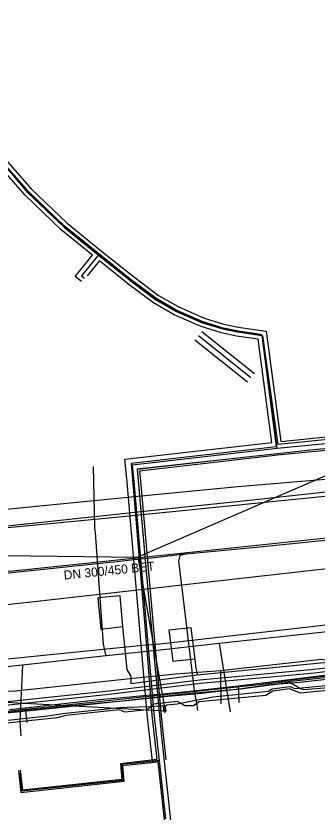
# Model space of a CAD drawing. Extents: x -600309 to -598967, y -1161267 to -1160292.
# Drawn here: x -599198.7 to -599172, y -1160445.7 to -1160375.2 of the extents above; entities that cross this region are included whole.
import ezdxf

# ---------------------------------------------------------------- set-up
doc = ezdxf.new("R2010")
doc.units = 0
for name, color, linetype in [('Vrstva 12', 7, 'Continuous'), ('Vrstva 13', 7, 'Continuous'), ('Vrstva 19', 7, 'Continuous'), ('Vrstva 25', 7, 'Continuous'), ('Vrstva 26', 7, 'Continuous'), ('Vrstva 29', 7, 'Continuous'), ('Vrstva 30', 7, 'Continuous'), ('Vrstva 37', 7, 'Continuous'), ('Vrstva 42', 7, 'Continuous'), ('Vrstva 44', 7, 'Continuous'), ('Vrstva 51', 7, 'Continuous'), ('Vrstva 54', 7, 'Continuous'), ('Vrstva 55', 7, 'Continuous'), ('Vrstva 58', 7, 'Continuous'), ('Vrstva 9', 7, 'Continuous')]:
    doc.layers.add(name, color=color, linetype=linetype)

msp = doc.modelspace()

# ---------------------------------------------------------------- linework, layer by layer
at = {"layer": 'Vrstva 12'}
for points in [[(-599159.73, -1160416.58), (-599172.75, -1160417.89), (-599175.74, -1160418.2), (-599179.22, -1160418.55), (-599185.69, -1160419.2), (-599191.36, -1160419.77)], [(-599215.54, -1160422.07), (-599183.99, -1160418.7), (-599177.99, -1160418.06), (-599168.25, -1160417.02), (-599166.51, -1160416.87)], [(-599191.36, -1160419.77), (-599215.54, -1160422.07)], [(-599156.38, -1160431.75), (-599177.29, -1160434.36)], [(-599166.63, -1160433.18), (-599175.04, -1160434.11), (-599177.29, -1160434.36)], [(-599177.29, -1160434.36), (-599178.99, -1160434.55)], [(-599184.72, -1160435.16), (-599186.42, -1160435.32)], [(-599183.23, -1160435.02), (-599184.72, -1160435.16)], [(-599178.99, -1160434.55), (-599182.96, -1160435), (-599183.23, -1160435.02)], [(-599178.99, -1160434.55), (-599178.92, -1160436.01)], [(-599188.61, -1160435.52), (-599191.28, -1160435.77), (-599197.85, -1160436.5)], [(-599186.42, -1160435.32), (-599188.61, -1160435.52)], [(-599197.85, -1160436.5), (-599199.24, -1160436.65)], [(-599197.85, -1160436.5), (-599197.73, -1160437.78)]]:
    msp.add_lwpolyline(points, dxfattribs=at)
at = {"layer": 'Vrstva 13'}
msp.add_line((-599180.669, -1160430.786), (-599179.696, -1160436.841), dxfattribs=at)
for points in [[(-599190.684, -1160431.876), (-599190.766, -1160431.5), (-599190.916, -1160430.824), (-599191.624, -1160420.957), (-599191.685, -1160420.493), (-599191.81, -1160415.087)], [(-599266.29, -1160439), (-599265.75, -1160438.92), (-599254.31, -1160437.84), (-599242.55, -1160436.65), (-599224.43, -1160434.75), (-599206.75, -1160432.86), (-599187.429, -1160430.934), (-599185.94, -1160430.79), (-599176.34, -1160429.72), (-599164.53, -1160428.34), (-599160.25, -1160427.86), (-599155.91, -1160427.47), (-599154.382, -1160427.282)], [(-599149.54, -1160427.41), (-599153.011, -1160427.773), (-599153.26, -1160427.8), (-599160.957, -1160428.64), (-599180.669, -1160430.786), (-599185.884, -1160431.357), (-599187.377, -1160431.521), (-599190.684, -1160431.876), (-599198.113, -1160432.685), (-599222.346, -1160435.322), (-599251.335, -1160438.478), (-599265.5, -1160440.02), (-599266.034, -1160440.08)], [(-599198.113, -1160432.685), (-599198.348, -1160437.726), (-599198.25, -1160438.947)]]:
    msp.add_lwpolyline(points, dxfattribs=at)
at = {"layer": 'Vrstva 19'}
for points in [[(-599185.219, -1160423.02), (-599184.89, -1160422.97), (-599184.02, -1160422.87), (-599183.6, -1160422.83), (-599176.76, -1160422.18), (-599169.86, -1160421.48), (-599162.91, -1160420.74), (-599159.94, -1160420.4), (-599159.46, -1160420.35), (-599158.7, -1160420.24), (-599157.37, -1160420.1), (-599154.21, -1160419.74), (-599153.17, -1160419.62), (-599152.28, -1160419.52), (-599151.55, -1160419.44)], [(-599189.94, -1160423.53), (-599189.51, -1160423.49), (-599188.21, -1160423.34), (-599186.92, -1160423.2), (-599185.62, -1160423.06), (-599185.219, -1160423.02)], [(-599183.6, -1160422.83), (-599184.16, -1160422.97), (-599184.28, -1160423.44), (-599183.09, -1160433.19), (-599182.95, -1160434.4), (-599182.91, -1160434.67), (-599182.91, -1160434.72), (-599182.89, -1160434.84), (-599182.87, -1160434.97), (-599182.69, -1160436.05), (-599182.58, -1160436.71)], [(-599254.51, -1160430.31), (-599245.92, -1160429.36), (-599243.04, -1160429.08), (-599229.67, -1160427.65), (-599217.1, -1160426.32), (-599203.43, -1160424.93), (-599200.2, -1160424.61), (-599192.59, -1160423.81), (-599191.52, -1160423.69), (-599190.92, -1160423.63), (-599190.43, -1160423.58), (-599189.94, -1160423.53)]]:
    msp.add_lwpolyline(points, dxfattribs=at)
at = {"layer": 'Vrstva 25'}
for p, q in [((-599161.519, -1160412.108), (-599175.528, -1160413.501)), ((-599185.993, -1160441.133), (-599185.429, -1160446.319))]:
    msp.add_line(p, q, dxfattribs=at)
for points in [[(-599191.346, -1160396.32), (-599194.404, -1160393.82), (-599197.616, -1160390.754), (-599199.666, -1160388.406), (-599200.989, -1160386.783), (-599209.232, -1160391.952), (-599215.053, -1160395.52), (-599219.636, -1160397.611), (-599223.7, -1160398.633), (-599236.871, -1160400.827), (-599242.951, -1160401.557), (-599244.194, -1160401.609), (-599248.324, -1160401.546), (-599253.382, -1160400.553), (-599257.817, -1160398.049), (-599260.079, -1160396.059), (-599264.436, -1160400.845), (-599269.275, -1160406.227), (-599292.639, -1160384.894), (-599305.234, -1160397.5)], [(-599191.346, -1160396.32), (-599192.863, -1160398.187), (-599192.605, -1160398.4)], [(-599175.528, -1160413.501), (-599176.867, -1160403.463), (-599179.051, -1160403.143), (-599180.361, -1160402.861), (-599182.125, -1160402.311), (-599184.484, -1160401.282), (-599186.254, -1160400.26), (-599188.39, -1160398.672), (-599191.346, -1160396.32)], [(-599175.528, -1160413.501), (-599188.376, -1160414.974), (-599188.238, -1160416.414)], [(-599188.238, -1160416.414), (-599186.446, -1160436.975), (-599185.993, -1160441.133)], [(-599185.993, -1160441.133), (-599189.317, -1160441.495), (-599189.166, -1160442.902), (-599198.169, -1160443.872), (-599198.336, -1160442.3)]]:
    msp.add_lwpolyline(points, dxfattribs=at)
at = {"layer": 'Vrstva 26'}
for p, q in [((-599191.285, -1160396.88), (-599192.365, -1160398.208)), ((-599175.209, -1160412.867), (-599161.578, -1160411.51)), ((-599161.46, -1160412.705), (-599175.46, -1160414.097))]:
    msp.add_line(p, q, dxfattribs=at)
for points in [[(-599305.517, -1160397.218), (-599292.651, -1160384.34), (-599269.303, -1160405.66), (-599264.732, -1160400.577), (-599260.11, -1160395.499), (-599257.584, -1160397.721), (-599253.242, -1160400.173), (-599248.282, -1160401.147), (-599244.199, -1160401.209), (-599242.983, -1160401.158), (-599236.928, -1160400.43), (-599223.782, -1160398.241), (-599219.769, -1160397.232), (-599215.242, -1160395.166), (-599209.443, -1160391.612), (-599200.903, -1160386.256), (-599199.361, -1160388.148), (-599197.326, -1160390.477), (-599194.139, -1160393.52), (-599191.092, -1160396.011)], [(-599191.908, -1160396.377), (-599194.669, -1160394.12), (-599197.905, -1160391.031), (-599199.972, -1160388.664), (-599201.076, -1160387.309), (-599209.021, -1160392.292), (-599214.865, -1160395.873), (-599219.504, -1160397.99), (-599223.618, -1160399.025), (-599236.814, -1160401.223), (-599242.918, -1160401.956), (-599244.189, -1160402.01), (-599248.365, -1160401.946), (-599253.522, -1160400.933), (-599258.05, -1160398.377), (-599260.048, -1160396.619), (-599264.139, -1160401.114), (-599269.247, -1160406.795), (-599292.626, -1160385.447), (-599304.951, -1160397.783)], [(-599191.096, -1160396.007), (-599188.146, -1160398.355), (-599186.034, -1160399.925), (-599184.304, -1160400.925), (-599181.985, -1160401.935), (-599180.26, -1160402.474), (-599178.979, -1160402.749), (-599176.511, -1160403.111), (-599175.209, -1160412.867)], [(-599192.859, -1160398.709), (-599193.424, -1160398.242), (-599191.908, -1160396.377)], [(-599176.005, -1160412.952), (-599177.224, -1160403.815), (-599179.122, -1160403.537), (-599180.463, -1160403.248), (-599182.264, -1160402.686), (-599184.665, -1160401.64), (-599186.474, -1160400.595), (-599188.634, -1160398.989), (-599191.285, -1160396.88)], [(-599188.835, -1160416.472), (-599189.03, -1160414.445), (-599176.005, -1160412.952)], [(-599175.46, -1160414.097), (-599187.723, -1160415.503), (-599187.641, -1160416.357)], [(-599186.59, -1160441.198), (-599187.043, -1160437.033), (-599188.836, -1160416.466)], [(-599187.64, -1160416.362), (-599185.849, -1160436.916), (-599185.397, -1160441.068)]]:
    msp.add_lwpolyline(points, dxfattribs=at)
at = {"layer": 'Vrstva 29'}
msp.add_line((-599177.854, -1160407.23), (-599182.506, -1160403.517), dxfattribs=at)
at = {"layer": 'Vrstva 30'}
for p, q in [((-599182.194, -1160403.126), (-599177.542, -1160406.839)), ((-599178.166, -1160407.621), (-599182.818, -1160403.908))]:
    msp.add_line(p, q, dxfattribs=at)
at = {"layer": 'Vrstva 37'}
for points in [[(-599168.806, -1160355.791), (-599166.577, -1160378.573), (-599168.064, -1160378.723), (-599167.911, -1160380.323), (-599166.42, -1160380.169), (-599164.278, -1160401.866), (-599162.592, -1160401.69), (-599161.605, -1160411.763), (-599175.439, -1160413.144), (-599176.797, -1160403.514), (-599177.012, -1160403.403), (-599178.975, -1160403.114), (-599180.425, -1160402.795), (-599182.181, -1160402.24), (-599184.478, -1160401.237), (-599186.279, -1160400.181), (-599188.425, -1160398.582), (-599194.409, -1160393.777), (-599197.565, -1160390.718), (-599199.716, -1160388.279)], [(-599200.984, -1160386.874), (-599197.646, -1160390.813), (-599194.391, -1160393.901), (-599190.914, -1160396.715), (-599188.228, -1160398.851), (-599186.268, -1160400.305), (-599184.45, -1160401.346), (-599182.15, -1160402.347), (-599180.342, -1160402.902), (-599179.045, -1160403.17), (-599176.895, -1160403.495), (-599175.615, -1160413.347), (-599188.47, -1160414.815), (-599187.027, -1160432.066), (-599186.626, -1160437.119), (-599186.186, -1160441.058), (-599189.424, -1160441.425), (-599189.282, -1160442.813), (-599198.082, -1160443.774), (-599198.283, -1160441.997)], [(-599088.539, -1160415.426), (-599122.332, -1160419.036), (-599140.386, -1160421.033), (-599141.325, -1160410.634), (-599141.674, -1160410.408), (-599151.481, -1160411.332), (-599151.839, -1160411.626), (-599162.058, -1160412.619), (-599172.281, -1160413.614), (-599180.114, -1160414.479), (-599187.943, -1160415.343), (-599186.98, -1160426.029)], [(-599186.98, -1160426.029), (-599185.802, -1160438.745), (-599183.829, -1160457.165), (-599196.763, -1160458.819), (-599194.945, -1160472.959), (-599193.092, -1160487.344), (-599191.832, -1160497.004), (-599189.085, -1160518.698), (-599184.645, -1160518.094), (-599182.287, -1160536.371), (-599186.773, -1160536.904), (-599185.919, -1160543.243)], [(-599198.457, -1160442.034), (-599198.247, -1160443.967), (-599189.076, -1160442.981), (-599189.222, -1160441.572), (-599186.106, -1160441.245), (-599184.414, -1160456.718), (-599197.081, -1160458.375), (-599197.31, -1160458.81), (-599193.65, -1160487.388), (-599192.376, -1160497.298), (-599189.502, -1160519.009), (-599189.296, -1160519.241), (-599185.431, -1160518.76), (-599184.944, -1160519.277), (-599182.893, -1160535.5), (-599183.306, -1160535.953), (-599187.068, -1160536.425), (-599187.322, -1160536.835), (-599185.599, -1160549.426), (-599183.312, -1160561.946), (-599181.269, -1160572.198), (-599177.909, -1160571.51)]]:
    msp.add_lwpolyline(points, dxfattribs=at)
at = {"layer": 'Vrstva 42'}
for points in [[(-599168.81, -1160355.79), (-599166.58, -1160378.57), (-599168.06, -1160378.72), (-599167.91, -1160380.32), (-599166.42, -1160380.17), (-599164.28, -1160401.87), (-599162.59, -1160401.69), (-599161.6, -1160411.76), (-599175.44, -1160413.14), (-599176.8, -1160403.51), (-599177.01, -1160403.4), (-599178.98, -1160403.11), (-599180.42, -1160402.8), (-599182.18, -1160402.24), (-599184.48, -1160401.24), (-599186.28, -1160400.18), (-599188.43, -1160398.58), (-599194.41, -1160393.78), (-599197.57, -1160390.72), (-599199.72, -1160388.28)], [(-599204.62, -1160419.36), (-599194.46, -1160418.36), (-599186.67, -1160417.6), (-599179.02, -1160416.87), (-599170.52, -1160416.16), (-599162.01, -1160415.26), (-599159.641, -1160414.949), (-599155.38, -1160414.39), (-599154.85, -1160413.88), (-599154.71, -1160413.29), (-599155.17, -1160410.09), (-599155.66, -1160404.47), (-599155.67, -1160402.75), (-599156.47, -1160395.46), (-599157.68, -1160384.84), (-599157.98, -1160382.06), (-599157.751, -1160381.455), (-599157.593, -1160381.04), (-599157.1, -1160379.74), (-599157.05, -1160379.447), (-599156.92, -1160378.68), (-599157.15, -1160377.67), (-599157.288, -1160377.328), (-599157.49, -1160376.83)], [(-599200.98, -1160386.87), (-599197.65, -1160390.81), (-599194.39, -1160393.9), (-599190.91, -1160396.71), (-599188.23, -1160398.85), (-599186.27, -1160400.31), (-599184.45, -1160401.35), (-599182.15, -1160402.35), (-599180.34, -1160402.9), (-599179.04, -1160403.17), (-599176.89, -1160403.49), (-599175.62, -1160413.35), (-599188.47, -1160414.82), (-599187.03, -1160432.07), (-599186.63, -1160437.12), (-599186.19, -1160441.06), (-599189.42, -1160441.43), (-599189.28, -1160442.81), (-599198.08, -1160443.77), (-599198.28, -1160442)], [(-599088.54, -1160415.43), (-599122.33, -1160419.04), (-599140.39, -1160421.03), (-599141.33, -1160410.63), (-599141.67, -1160410.41), (-599151.48, -1160411.33), (-599151.84, -1160411.63), (-599162.06, -1160412.62), (-599172.28, -1160413.61), (-599180.11, -1160414.48), (-599187.94, -1160415.34), (-599186.98, -1160426.03), (-599185.8, -1160438.75), (-599183.83, -1160457.16), (-599196.76, -1160458.82), (-599194.94, -1160472.96)], [(-599188.51, -1160433.65), (-599188.83, -1160433.07), (-599189.2, -1160429.27), (-599189.45, -1160426.54), (-599191.41, -1160426.72), (-599191.17, -1160429.49), (-599189.2, -1160429.27)], [(-599182.7, -1160433.01), (-599182.8, -1160432.12), (-599183.16, -1160429.38), (-599185.13, -1160429.59), (-599184.76, -1160432.34), (-599182.8, -1160432.12)], [(-599182.7, -1160433.01), (-599182.617, -1160433.552), (-599171.072, -1160432.425), (-599169.629, -1160432.272), (-599166.032, -1160431.909), (-599164.675, -1160431.253), (-599160.068, -1160430.698), (-599159.039, -1160430.839)], [(-599220.527, -1160438.141), (-599190.459, -1160434.977), (-599182.366, -1160433.991), (-599172.256, -1160433.061), (-599164.877, -1160432.162)], [(-599220.527, -1160438.141), (-599190.459, -1160434.977), (-599182.366, -1160433.991), (-599172.256, -1160433.061), (-599164.877, -1160432.162)], [(-599220.495, -1160438.439), (-599190.425, -1160435.275), (-599182.334, -1160434.289), (-599172.224, -1160433.359), (-599164.823, -1160432.458)], [(-599220.495, -1160438.439), (-599190.425, -1160435.275), (-599182.334, -1160434.289), (-599172.224, -1160433.359), (-599164.823, -1160432.458)], [(-599156.887, -1160433.804), (-599156.881, -1160433.343), (-599157.862, -1160433.354), (-599158.455, -1160433.361), (-599164.872, -1160434.096), (-599165.409, -1160434.373), (-599173.447, -1160435.181), (-599174.43, -1160434.776), (-599175.9, -1160434.986), (-599176.534, -1160435.376), (-599182.45, -1160435.954), (-599182.947, -1160436.293), (-599183.704, -1160436.285), (-599184.1, -1160436.064), (-599184.362, -1160435.918), (-599186.496, -1160436.146), (-599186.711, -1160436.346), (-599187.051, -1160436.662), (-599189.025, -1160436.843), (-599189.516, -1160436.644), (-599194.269, -1160437.149), (-599195.02, -1160437.346), (-599200.94, -1160437.987)], [(-599188.51, -1160433.65), (-599188.506, -1160434.319), (-599182.617, -1160433.552)], [(-599203.78, -1160438.04), (-599195.86, -1160437.19), (-599194.305, -1160436.952), (-599189.487, -1160436.44), (-599188.81, -1160436.4), (-599186.711, -1160436.346), (-599186.409, -1160436.338), (-599185.703, -1160436.263), (-599185.657, -1160436.304), (-599185.564, -1160436.761), (-599185.445, -1160436.848), (-599185.368, -1160436.73), (-599185.455, -1160436.321), (-599185.31, -1160436.22), (-599184.404, -1160436.124), (-599184.1, -1160436.064), (-599181.24, -1160435.5), (-599176.296, -1160434.995), (-599175.969, -1160434.794), (-599174.404, -1160434.57), (-599173.952, -1160434.757), (-599167.01, -1160434.07)], [(-599198.46, -1160442.03), (-599198.25, -1160443.97), (-599189.08, -1160442.98), (-599189.22, -1160441.57), (-599186.11, -1160441.24), (-599184.41, -1160456.72), (-599197.08, -1160458.38), (-599197.31, -1160458.81), (-599193.65, -1160487.39), (-599192.38, -1160497.3), (-599189.5, -1160519.01), (-599189.3, -1160519.24), (-599185.43, -1160518.76), (-599184.94, -1160519.28), (-599182.89, -1160535.5), (-599183.31, -1160535.95), (-599187.07, -1160536.42), (-599187.32, -1160536.84), (-599185.6, -1160549.43), (-599183.31, -1160561.95), (-599181.27, -1160572.2), (-599177.91, -1160571.51)]]:
    msp.add_lwpolyline(points, dxfattribs=at)
at = {"layer": 'Vrstva 44'}
msp.add_lwpolyline([(-599206.3, -1160437.6), (-599196.83, -1160436.66), (-599189.27, -1160435.85), (-599183.78, -1160435.23), (-599178.77, -1160434.78), (-599174.5, -1160434.23), (-599174.38, -1160434.24), (-599173.45, -1160434.77), (-599173.16, -1160434.84), (-599171.35, -1160434.71), (-599165.06, -1160433.95), (-599160.31, -1160433.43), (-599160.094, -1160433.043), (-599159.971, -1160432.552), (-599160.094, -1160432.111), (-599160.965, -1160431.324), (-599160.966, -1160431.323)], dxfattribs=at)
at = {"layer": 'Vrstva 51'}
msp.add_lwpolyline([(-599200.27, -1160436.95), (-599197.39, -1160436.65), (-599193.73, -1160436.28), (-599188.6, -1160435.8), (-599185.22, -1160435.44), (-599182.23, -1160435.17), (-599178.89, -1160434.78), (-599176.39, -1160434.45), (-599173.54, -1160434.19), (-599170.59, -1160433.88), (-599167.81, -1160433.53), (-599165.28, -1160433.28), (-599162.93, -1160432.99), (-599160.6, -1160433.01), (-599159.56, -1160433.22), (-599157.53, -1160433.19), (-599153.06, -1160432.68), (-599150.986, -1160433.354), (-599150.14, -1160433.34)], dxfattribs=at)
at = {"layer": 'Vrstva 54'}
for points in [[(-599169.72, -1160415.27), (-599187.89, -1160423.11), (-599185.46, -1160436.78), (-599206.61, -1160435.61), (-599235.92, -1160438.42), (-599255.65, -1160440.37), (-599278.3, -1160442.74)], [(-599164.13, -1160421.49), (-599168.895, -1160421.191), (-599199.21, -1160424.4), (-599206.941, -1160422.893)], [(-599206.941, -1160422.893), (-599187.89, -1160423.11)]]:
    msp.add_lwpolyline(points, dxfattribs=at)
at = {"layer": 'Vrstva 55'}
msp.add_lwpolyline([(-599158.51, -1160377.27), (-599156.45, -1160376.91), (-599152.68, -1160413.45), (-599153.51, -1160415.11), (-599159.08, -1160416.06), (-599158.61, -1160432.05), (-599158.64, -1160432.34), (-599170.407, -1160433.724), (-599170.576, -1160432.141), (-599170.407, -1160433.724), (-599202.89, -1160437.14), (-599203.343, -1160435.509), (-599202.89, -1160437.14), (-599234.882, -1160440.475), (-599235.01, -1160439.55)], dxfattribs=at)
at = {"layer": 'Vrstva 58'}
for points in [[(-599158.05, -1160430.73), (-599160.65, -1160431.2), (-599169.19, -1160432.07), (-599170.594, -1160432.356), (-599171.6, -1160432.2), (-599180.56, -1160433.2)], [(-599180.56, -1160433.2), (-599184.549, -1160433.493), (-599188.02, -1160433.85), (-599198.71, -1160435.01), (-599202.08, -1160435.15), (-599204.03, -1160435.28), (-599208.44, -1160435.95), (-599221.33, -1160437.31), (-599231.04, -1160438.37), (-599232.78, -1160438.66), (-599234.96, -1160438.6), (-599250.03, -1160440.29), (-599252.01, -1160440.53), (-599252.01, -1160440.53), (-599254.004, -1160440.688), (-599255.8, -1160440.83)], [(-599180.56, -1160433.2), (-599180.51, -1160436.13)]]:
    msp.add_lwpolyline(points, dxfattribs=at)
at = {"layer": 'Vrstva 9'}
for p, q in [((-599197.08, -1160427.04), (-599153.99, -1160422.22)), ((-599240.2, -1160431.74), (-599197.08, -1160427.04))]:
    msp.add_line(p, q, dxfattribs=at)

# ---------------------------------------------------------------- texts
at = {"layer": 'Vrstva 12'}
msp.add_text('DN 300/450 BET', height=0.8, rotation=5.78687, dxfattribs=at).set_placement((-599194.407, -1160425.117))

doc.saveas('drawing.dxf')
